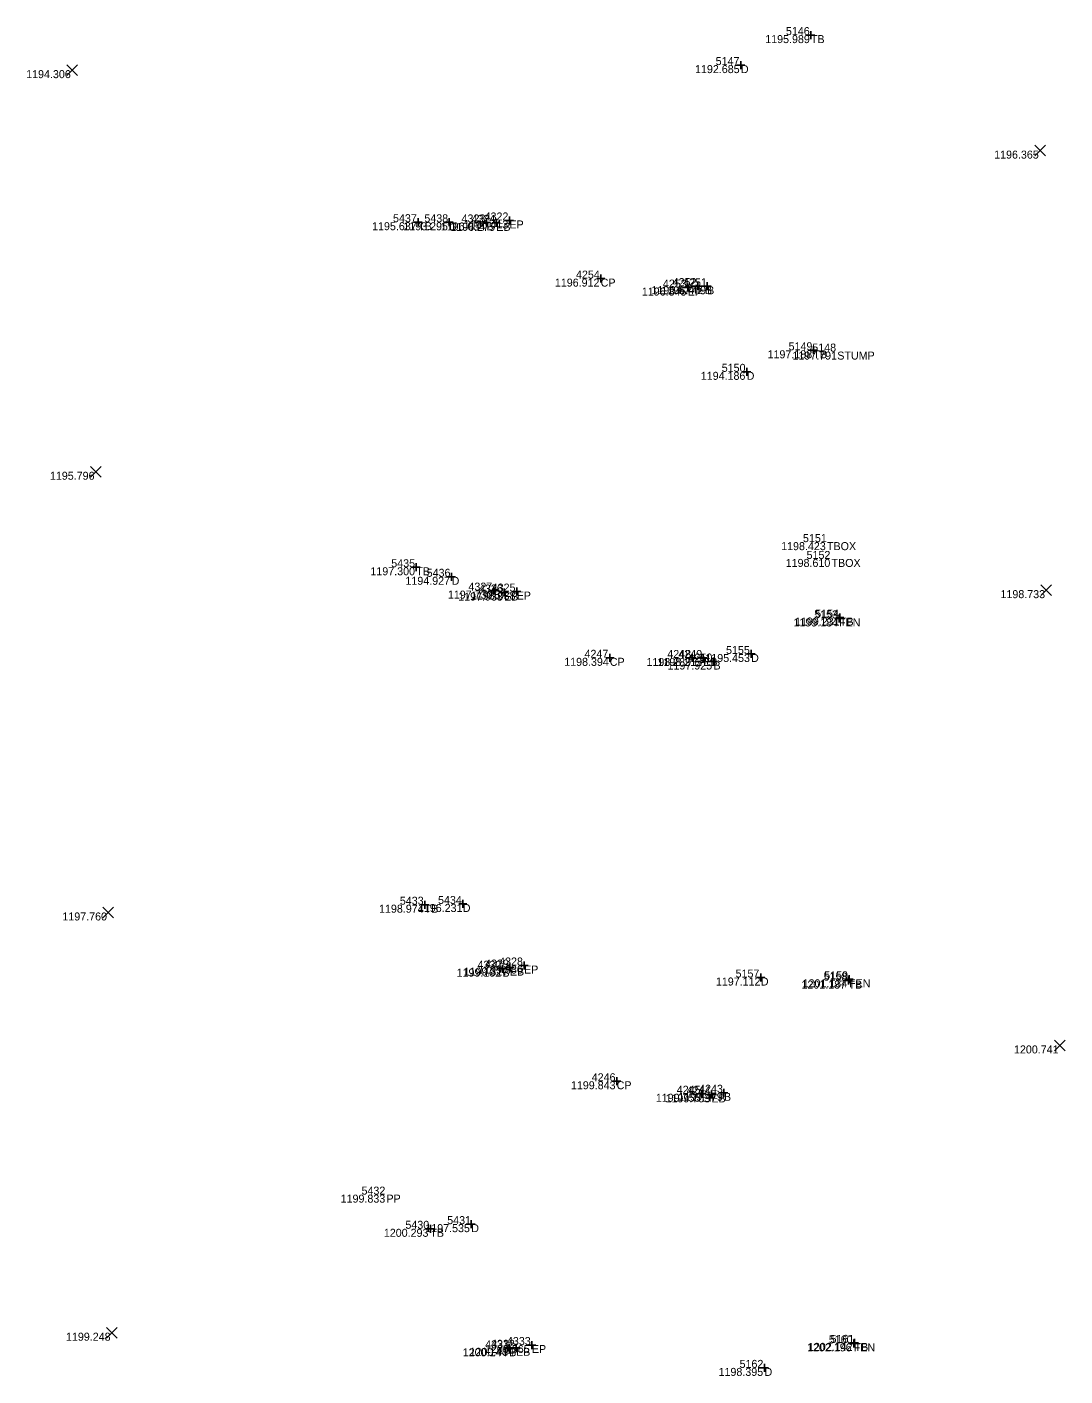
# Model space of a CAD drawing. Extents: x 2044997 to 2050342, y 455233 to 458054.
# Drawn here: x 2047547.8 to 2047677.7, y 457525.3 to 457694 of the extents above; entities that cross this region are included whole.
import ezdxf

# ---------------------------------------------------------------- set-up
doc = ezdxf.new("R2010")
doc.units = 0
for name, color, linetype in [('SV_X_Random_Point', 7, 'Continuous'), ('SV_X_Shot_Marker', 7, 'Continuous'), ('SV_X_Text_Comment', 7, 'Continuous'), ('SV_X_Text_Elevation', 7, 'Continuous'), ('SV_X_Text_Name', 7, 'Continuous')]:
    doc.layers.add(name, color=color, linetype=linetype)

msp = doc.modelspace()

# ---------------------------------------------------------------- linework, layer by layer
at = {"layer": 'SV_X_Random_Point'}
for p, q in [((2047552.8, 457687.9), (2047554.13, 457689.23)), ((2047552.8, 457689.23), (2047554.13, 457687.9)), ((2047673.87, 457677.84), (2047675.2, 457679.18)), ((2047673.87, 457679.18), (2047675.2, 457677.84)), ((2047555.77, 457637.71), (2047557.1, 457639.04)), ((2047555.77, 457639.04), (2047557.1, 457637.71)), ((2047674.64, 457622.9), (2047675.97, 457624.24)), ((2047674.64, 457624.24), (2047675.97, 457622.9)), ((2047557.32, 457582.61), (2047558.66, 457583.95)), ((2047557.32, 457583.95), (2047558.66, 457582.61)), ((2047676.32, 457565.99), (2047677.65, 457567.33)), ((2047676.32, 457567.33), (2047677.65, 457565.99)), ((2047557.77, 457530.08), (2047559.11, 457531.42)), ((2047557.77, 457531.42), (2047559.11, 457530.08))]:
    msp.add_line(p, q, dxfattribs=at)
at = {"layer": 'SV_X_Shot_Marker'}
for p, q in [((2047645.37, 457692.95), (2047646.37, 457692.95)), ((2047645.87, 457693.45), (2047645.87, 457692.45)), ((2047645.87, 457692.95), (2047645.87, 457692.95)), ((2047637.12, 457689.7), (2047637.12, 457688.7)), ((2047636.62, 457689.2), (2047637.62, 457689.2)), ((2047637.12, 457689.2), (2047637.12, 457689.2)), ((2047596.27, 457669.56), (2047597.27, 457669.56)), ((2047596.77, 457670.06), (2047596.77, 457669.06)), ((2047596.77, 457669.56), (2047596.77, 457669.56)), ((2047600.14, 457669.55), (2047601.14, 457669.55)), ((2047600.64, 457670.05), (2047600.64, 457669.05)), ((2047600.64, 457669.55), (2047600.64, 457669.55)), ((2047604.78, 457669.53), (2047605.78, 457669.53)), ((2047605.28, 457670.03), (2047605.28, 457669.03)), ((2047605.28, 457669.53), (2047605.28, 457669.53)), ((2047606.02, 457669.48), (2047607.02, 457669.48)), ((2047606.52, 457669.98), (2047606.52, 457668.98)), ((2047606.52, 457669.48), (2047606.52, 457669.48)), ((2047607.67, 457669.78), (2047608.67, 457669.78)), ((2047608.17, 457670.28), (2047608.17, 457669.28)), ((2047608.17, 457669.78), (2047608.17, 457669.78)), ((2047619.58, 457663.01), (2047619.58, 457662.01)), ((2047619.08, 457662.51), (2047620.08, 457662.51)), ((2047619.58, 457662.51), (2047619.58, 457662.51)), ((2047629.97, 457661.39), (2047630.97, 457661.39)), ((2047630.47, 457661.89), (2047630.47, 457660.89)), ((2047630.47, 457661.39), (2047630.47, 457661.39)), ((2047631.21, 457661.57), (2047632.21, 457661.57)), ((2047631.71, 457662.07), (2047631.71, 457661.07)), ((2047631.71, 457661.57), (2047631.71, 457661.57)), ((2047632.39, 457661.55), (2047633.39, 457661.55)), ((2047632.89, 457662.05), (2047632.89, 457661.05)), ((2047632.89, 457661.55), (2047632.89, 457661.55)), ((2047645.68, 457653.55), (2047646.68, 457653.55)), ((2047646.18, 457654.05), (2047646.18, 457653.05)), ((2047646.18, 457653.55), (2047646.18, 457653.55)), ((2047637.34, 457650.86), (2047638.34, 457650.86)), ((2047637.84, 457651.36), (2047637.84, 457650.36)), ((2047637.84, 457650.86), (2047637.84, 457650.86)), ((2047596.02, 457626.43), (2047597.02, 457626.43)), ((2047596.52, 457626.93), (2047596.52, 457625.93)), ((2047596.52, 457626.43), (2047596.52, 457626.43)), ((2047600.94, 457625.74), (2047600.94, 457624.74)), ((2047600.44, 457625.24), (2047601.44, 457625.24)), ((2047600.94, 457625.24), (2047600.94, 457625.24)), ((2047606.2, 457624.01), (2047606.2, 457623.01)), ((2047609.08, 457623.89), (2047609.08, 457622.89)), ((2047605.7, 457623.51), (2047606.7, 457623.51)), ((2047606.2, 457623.51), (2047606.2, 457623.51)), ((2047606.99, 457623.27), (2047607.99, 457623.27)), ((2047607.49, 457623.77), (2047607.49, 457622.77)), ((2047607.49, 457623.27), (2047607.49, 457623.27)), ((2047608.58, 457623.39), (2047609.58, 457623.39)), ((2047609.08, 457623.39), (2047609.08, 457623.39)), ((2047649.39, 457620.53), (2047649.39, 457619.53)), ((2047649.5, 457620.65), (2047649.5, 457619.65)), ((2047648.89, 457620.03), (2047649.89, 457620.03)), ((2047649, 457620.15), (2047650, 457620.15)), ((2047649.39, 457620.03), (2047649.39, 457620.03)), ((2047649.5, 457620.15), (2047649.5, 457620.15)), ((2047620.72, 457615.61), (2047620.72, 457614.61)), ((2047631.03, 457615.59), (2047631.03, 457614.59)), ((2047632.4, 457615.59), (2047632.4, 457614.59)), ((2047637.89, 457615.59), (2047638.89, 457615.59)), ((2047638.39, 457616.09), (2047638.39, 457615.09)), ((2047638.39, 457615.59), (2047638.39, 457615.59)), ((2047620.22, 457615.11), (2047621.22, 457615.11)), ((2047620.72, 457615.11), (2047620.72, 457615.11)), ((2047630.53, 457615.09), (2047631.53, 457615.09)), ((2047631.03, 457615.09), (2047631.03, 457615.09)), ((2047631.9, 457615.09), (2047632.9, 457615.09)), ((2047632.4, 457615.09), (2047632.4, 457615.09)), ((2047633.19, 457614.65), (2047634.19, 457614.65)), ((2047633.69, 457615.15), (2047633.69, 457614.15)), ((2047633.69, 457614.65), (2047633.69, 457614.65)), ((2047597.07, 457584.25), (2047598.07, 457584.25)), ((2047597.57, 457584.75), (2047597.57, 457583.75)), ((2047597.57, 457584.25), (2047597.57, 457584.25)), ((2047601.83, 457584.34), (2047602.83, 457584.34)), ((2047602.33, 457584.84), (2047602.33, 457583.84)), ((2047602.33, 457584.34), (2047602.33, 457584.34)), ((2047607.29, 457576.75), (2047607.29, 457575.75)), ((2047608.22, 457576.89), (2047608.22, 457575.89)), ((2047609.5, 457576.65), (2047610.5, 457576.65)), ((2047610, 457577.15), (2047610, 457576.15)), ((2047610, 457576.65), (2047610, 457576.65)), ((2047606.79, 457576.25), (2047607.79, 457576.25)), ((2047607.29, 457576.25), (2047607.29, 457576.25)), ((2047607.72, 457576.39), (2047608.72, 457576.39)), ((2047608.22, 457576.39), (2047608.22, 457576.39)), ((2047639.11, 457575.15), (2047640.11, 457575.15)), ((2047639.61, 457575.65), (2047639.61, 457574.65)), ((2047639.61, 457575.15), (2047639.61, 457575.15)), ((2047650.14, 457574.93), (2047651.14, 457574.93)), ((2047650.57, 457575.26), (2047650.57, 457574.26)), ((2047650.64, 457575.43), (2047650.64, 457574.43)), ((2047650.64, 457574.93), (2047650.64, 457574.93)), ((2047650.07, 457574.76), (2047651.07, 457574.76)), ((2047650.57, 457574.76), (2047650.57, 457574.76)), ((2047621.08, 457562.18), (2047622.08, 457562.18)), ((2047621.58, 457562.68), (2047621.58, 457561.68)), ((2047621.58, 457562.18), (2047621.58, 457562.18)), ((2047631.72, 457560.62), (2047632.72, 457560.62)), ((2047632.22, 457561.12), (2047632.22, 457560.12)), ((2047632.22, 457560.62), (2047632.22, 457560.62)), ((2047632.92, 457560.54), (2047633.92, 457560.54)), ((2047633.42, 457561.04), (2047633.42, 457560.04)), ((2047633.42, 457560.54), (2047633.42, 457560.54)), ((2047634.5, 457560.74), (2047635.5, 457560.74)), ((2047635, 457561.24), (2047635, 457560.24)), ((2047635, 457560.74), (2047635, 457560.74)), ((2047603.39, 457544.82), (2047603.39, 457543.82)), ((2047597.78, 457543.74), (2047598.78, 457543.74)), ((2047598.28, 457544.24), (2047598.28, 457543.24)), ((2047598.28, 457543.74), (2047598.28, 457543.74)), ((2047602.89, 457544.32), (2047603.89, 457544.32)), ((2047603.39, 457544.32), (2047603.39, 457544.32)), ((2047608.99, 457529.36), (2047608.99, 457528.36)), ((2047610.97, 457529.71), (2047610.97, 457528.71)), ((2047650.73, 457529.41), (2047651.73, 457529.41)), ((2047650.83, 457529.48), (2047651.83, 457529.48)), ((2047651.23, 457529.91), (2047651.23, 457528.91)), ((2047651.23, 457529.41), (2047651.23, 457529.41)), ((2047651.33, 457529.98), (2047651.33, 457528.98)), ((2047651.33, 457529.48), (2047651.33, 457529.48)), ((2047607.64, 457528.8), (2047608.64, 457528.8)), ((2047608.14, 457529.3), (2047608.14, 457528.3)), ((2047608.14, 457528.8), (2047608.14, 457528.8)), ((2047608.49, 457528.86), (2047609.49, 457528.86)), ((2047608.99, 457528.86), (2047608.99, 457528.86)), ((2047610.47, 457529.21), (2047611.47, 457529.21)), ((2047610.97, 457529.21), (2047610.97, 457529.21)), ((2047639.57, 457526.35), (2047640.57, 457526.35)), ((2047640.07, 457526.85), (2047640.07, 457525.85)), ((2047640.07, 457526.35), (2047640.07, 457526.35))]:
    msp.add_line(p, q, dxfattribs=at)

# ---------------------------------------------------------------- texts
at = {"layer": 'SV_X_Text_Comment'}
for s, p in [('TB', (2047645.87, 457691.95)), ('D', (2047637.12, 457688.2)), ('TB', (2047596.77, 457668.56)), ('D', (2047600.64, 457668.55)), ('B', (2047605.28, 457668.53)), ('EB', (2047606.52, 457668.48)), ('EP', (2047608.17, 457668.78)), ('CP', (2047619.58, 457661.51)), ('EP', (2047630.47, 457660.39)), ('EB', (2047631.71, 457660.57)), ('B', (2047632.89, 457660.55)), ('TB', (2047646.18, 457652.55)), ('STUMP', (2047649.17, 457652.39)), ('D', (2047637.84, 457649.86)), ('TBOX', (2047647.88, 457628.57)), ('TBOX', (2047648.45, 457626.47)), ('TB', (2047596.52, 457625.43)), ('D', (2047600.94, 457624.24)), ('B', (2047606.2, 457622.51)), ('EB', (2047607.49, 457622.27)), ('EP', (2047609.08, 457622.39)), ('FEN', (2047649.39, 457619.03)), ('TB', (2047649.5, 457619.15)), ('D', (2047638.39, 457614.59)), ('CP', (2047620.72, 457614.11)), ('EP', (2047631.03, 457614.09)), ('EB', (2047632.4, 457614.09)), ('B', (2047633.69, 457613.65)), ('TB', (2047597.57, 457583.25)), ('D', (2047602.33, 457583.34)), ('EP', (2047610, 457575.65)), ('B', (2047607.29, 457575.25)), ('EB', (2047608.22, 457575.39)), ('D', (2047639.61, 457574.15)), ('FEN', (2047650.64, 457573.93)), ('TB', (2047650.57, 457573.76)), ('CP', (2047621.58, 457561.18)), ('EP', (2047632.22, 457559.62)), ('EB', (2047633.42, 457559.54)), ('B', (2047635, 457559.74)), ('PP', (2047592.79, 457547.01)), ('TB', (2047598.28, 457542.74)), ('D', (2047603.39, 457543.32)), ('FEN', (2047651.23, 457528.41)), ('TB', (2047651.33, 457528.48)), ('B', (2047608.14, 457527.8)), ('EB', (2047608.99, 457527.86)), ('EP', (2047610.97, 457528.21)), ('D', (2047640.07, 457525.35))]:
    msp.add_text(s, height=1, dxfattribs=at).set_placement(p)
at = {"layer": 'SV_X_Text_Elevation'}
for s, p in [('1195.989', (2047640.16, 457691.95)), ('1194.306', (2047547.73, 457687.57)), ('1192.685', (2047631.38, 457688.2)), ('1196.365', (2047668.79, 457677.51)), ('1195.637', (2047590.99, 457668.56)), ('1193.295', (2047594.9, 457668.55)), ('1196.054', (2047599.58, 457668.53)), ('1196.275', (2047600.78, 457668.48)), ('1196.413', (2047602.45, 457668.78)), ('1196.912', (2047613.85, 457661.51)), ('1196.845', (2047624.73, 457660.39)), ('1196.677', (2047625.93, 457660.57)), ('1196.409', (2047627.18, 457660.55)), ('1197.188', (2047640.45, 457652.55)), ('1197.791', (2047643.56, 457652.39)), ('1194.186', (2047632.1, 457649.86)), ('1195.796', (2047550.7, 457637.37)), ('1198.423', (2047642.15, 457628.57)), ('1198.610', (2047642.72, 457626.47)), ('1197.300', (2047590.78, 457625.43)), ('1194.927', (2047595.16, 457624.24)), ('1197.730', (2047600.47, 457622.51)), ('1197.933', (2047601.76, 457622.27)), ('1198.038', (2047603.35, 457622.39)), ('1198.733', (2047669.58, 457622.57)), ('1199.184', (2047643.69, 457619.03)), ('1199.231', (2047643.88, 457619.15)), ('1195.453', (2047632.67, 457614.59)), ('1198.394', (2047615.02, 457614.11)), ('1198.289', (2047625.31, 457614.09)), ('1198.213', (2047626.68, 457614.09)), ('1197.925', (2047627.94, 457613.65)), ('1198.974', (2047591.86, 457583.25)), ('1196.231', (2047596.72, 457583.34)), ('1197.760', (2047552.26, 457582.28)), ('1199.386', (2047604.26, 457575.65)), ('1199.102', (2047601.56, 457575.25)), ('1199.317', (2047602.44, 457575.39)), ('1197.112', (2047633.99, 457574.15)), ('1201.134', (2047644.83, 457573.93)), ('1201.187', (2047644.69, 457573.76)), ('1200.741', (2047671.27, 457565.66)), ('1199.843', (2047615.86, 457561.18)), ('1199.755', (2047626.48, 457559.62)), ('1199.703', (2047627.69, 457559.54)), ('1199.479', (2047629.28, 457559.74)), ('1199.833', (2047587.06, 457547.01)), ('1200.293', (2047592.46, 457542.74)), ('1197.535', (2047597.65, 457543.32)), ('1199.248', (2047552.71, 457529.75)), ('1202.196', (2047645.39, 457528.41)), ('1202.142', (2047645.5, 457528.48)), ('1200.144', (2047602.33, 457527.8)), ('1200.434', (2047603.18, 457527.86)), ('1200.565', (2047605.12, 457528.21)), ('1198.395', (2047634.32, 457525.35))]:
    msp.add_text(s, height=1, dxfattribs=at).set_placement(p)
at = {"layer": 'SV_X_Text_Name'}
for s, p in [('5146', (2047642.75, 457692.95)), ('5147', (2047633.96, 457689.2)), ('5437', (2047593.61, 457669.56)), ('5438', (2047597.53, 457669.55)), ('4323', (2047602.18, 457669.53)), ('4324', (2047603.43, 457669.48)), ('4322', (2047605.06, 457669.78)), ('4254', (2047616.49, 457662.51)), ('4252', (2047628.59, 457661.57)), ('4253', (2047627.36, 457661.39)), ('4251', (2047629.89, 457661.55)), ('5149', (2047643.08, 457653.55)), ('5148', (2047646.05, 457653.39)), ('5150', (2047634.72, 457650.86)), ('5151', (2047644.88, 457629.57)), ('5435', (2047593.39, 457626.43)), ('5152', (2047645.33, 457627.47)), ('5436', (2047597.82, 457625.24)), ('4327', (2047603.04, 457623.51)), ('4326', (2047604.36, 457623.27)), ('4325', (2047605.95, 457623.39)), ('5153', (2047646.28, 457620.03)), ('5154', (2047646.41, 457620.15)), ('4247', (2047617.56, 457615.11)), ('4248', (2047627.91, 457615.09)), ('4249', (2047629.3, 457615.09)), ('4250', (2047630.57, 457614.65)), ('5155', (2047635.26, 457615.59)), ('5433', (2047594.46, 457584.25)), ('5434', (2047599.24, 457584.34)), ('4330', (2047604.17, 457576.25)), ('4329', (2047605.12, 457576.39)), ('4328', (2047606.88, 457576.65)), ('5157', (2047636.45, 457575.15)), ('5158', (2047647.45, 457574.76)), ('5159', (2047647.54, 457574.93)), ('4246', (2047618.46, 457562.18)), ('4245', (2047629.09, 457560.62)), ('4244', (2047630.33, 457560.54)), ('4243', (2047631.89, 457560.74)), ('5432', (2047589.67, 457548.01)), ('5430', (2047595.16, 457543.74)), ('5431', (2047600.39, 457544.32)), ('4331', (2047605.14, 457528.8)), ('4332', (2047605.87, 457528.86)), ('4333', (2047607.86, 457529.21)), ('5160', (2047648.11, 457529.41)), ('5161', (2047648.33, 457529.48)), ('5162', (2047636.95, 457526.35))]:
    msp.add_text(s, height=1, dxfattribs=at).set_placement(p)

doc.saveas('drawing.dxf')
